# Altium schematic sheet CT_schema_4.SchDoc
size 299 x 185 mm
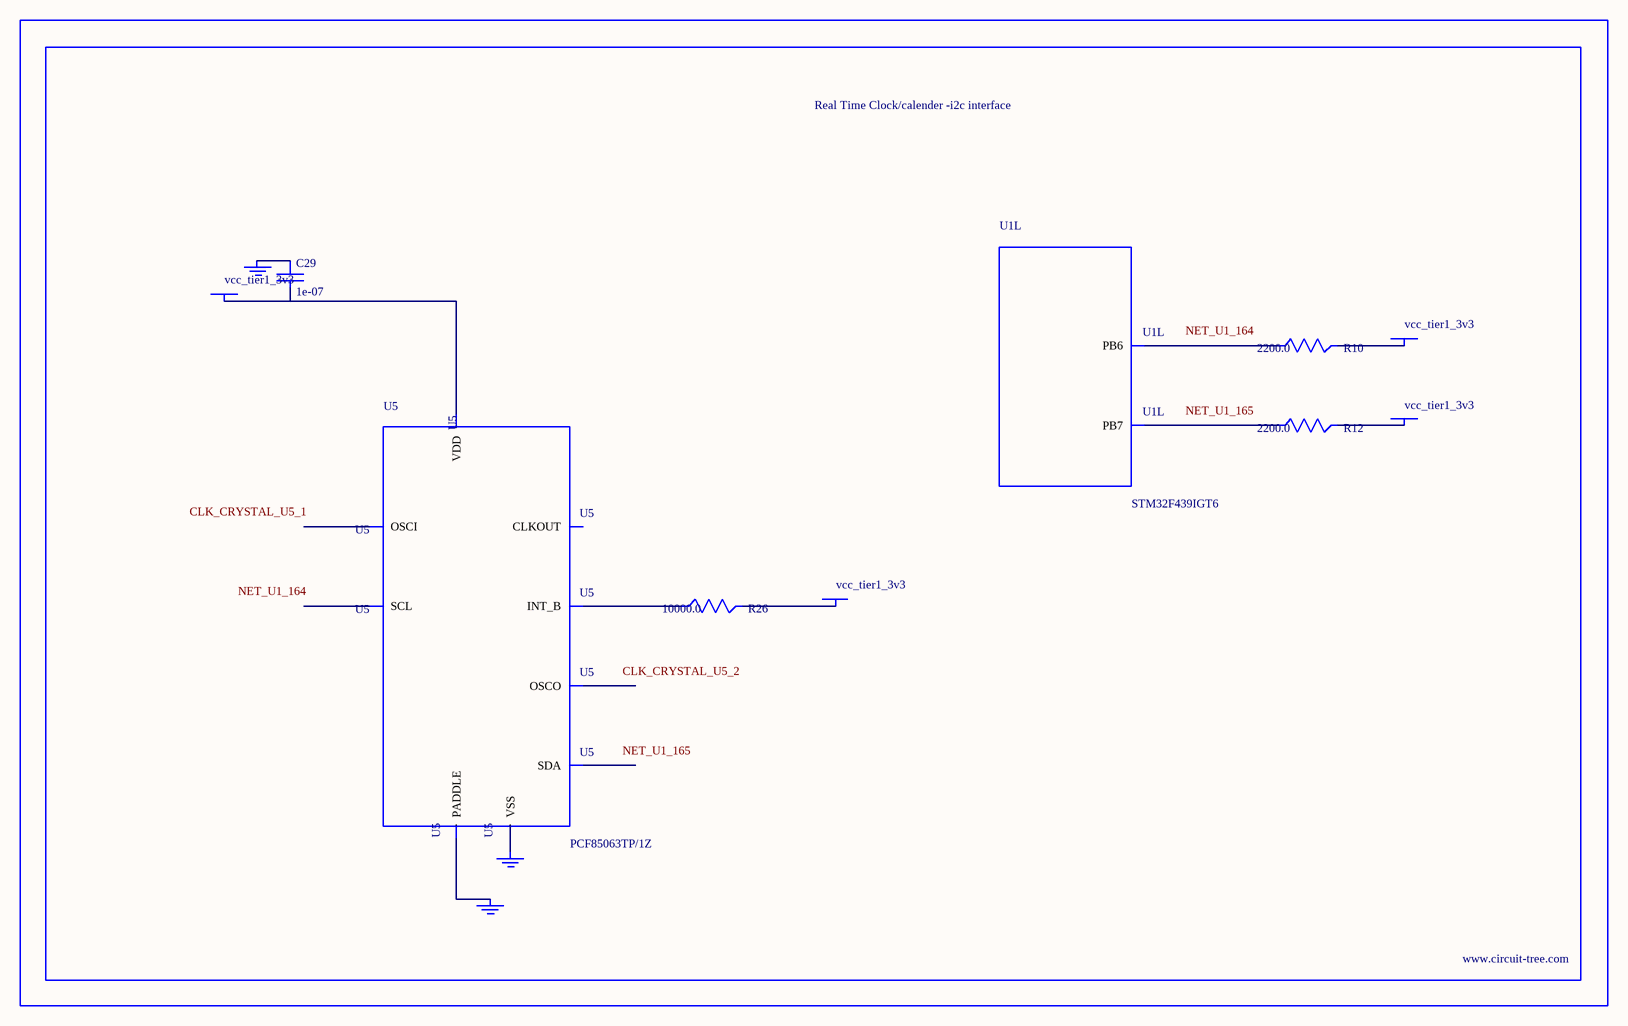
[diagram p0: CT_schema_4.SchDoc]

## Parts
BORDER3  (no value)
C29  1e-07  [C0402]
GND_INSTANCE_3_0  (no value)
GND_INSTANCE_3_1  (no value)
GND_INSTANCE_3_2  (no value)
POWER_INSTANCE_3_0  vcc_tier1_3v3
POWER_INSTANCE_3_1  vcc_tier1_3v3
POWER_INSTANCE_3_2  vcc_tier1_3v3
POWER_INSTANCE_3_3  vcc_tier1_3v3
R10  2200.0  [R0603]
R12  2200.0  [R0603]
R26  10000.0  [R0603]
U1  STM32F439IGT6  [LQFP176]  (part L of 14)
U5  PCF85063TP/1Z  [SON-8]

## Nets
NetC29_1: C29.1 GND_INSTANCE_3_0.0(GND)
NetC29_2: C29.2 POWER_INSTANCE_3_1.0(PWR) U5.8(VDD)
NetGND_INSTANCE_3_1_0: GND_INSTANCE_3_1.0(GND) U5.PAD(PADDLE)
NetGND_INSTANCE_3_2_0: GND_INSTANCE_3_2.0(GND) U5.4(VSS)
NetPOWER_INSTANCE_3_0_0: POWER_INSTANCE_3_0.0(PWR) R26.2
NetPOWER_INSTANCE_3_2_0: POWER_INSTANCE_3_2.0(PWR) R10.2
NetPOWER_INSTANCE_3_3_0: POWER_INSTANCE_3_3.0(PWR) R12.2
NetR10_1: R10.1 U1.164(PB6)
NetR12_1: R12.1 U1.165(PB7)
NetR26_1: R26.1 U5.3(INT_B)

Not connected (* = marked no-connect by the designer): U5 1(OSCI) 2(OSCO) 5(SDA) 6(SCL) 7(CLKOUT)

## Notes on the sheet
- Labels drawn without touching a wire or pin: CLK_CRYSTAL_U5_1, CLK_CRYSTAL_U5_2, NET_U1_164, NET_U1_165

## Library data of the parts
BORDER3 = BORDER_PAGE3
C29 = C0402C104K3RACTU
GND_INSTANCE_3_0-GND_INSTANCE_3_2 = GND
POWER_INSTANCE_3_0-POWER_INSTANCE_3_3 = PWR
R10 R12 = RC0603JR-072K2L
R26 = RC0603JR-0710KL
